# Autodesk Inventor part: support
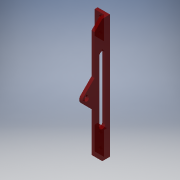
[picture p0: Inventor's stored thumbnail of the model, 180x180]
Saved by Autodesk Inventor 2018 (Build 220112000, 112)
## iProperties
Created: 2023-12
Part Number: support
Material: Generic
Document SubType Name: Modeling
Designer: DDUGKY
Density: 1 g/cm^3
Appearance: Default
Author: DDUGKY
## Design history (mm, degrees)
sketch "Sketch1"
  geometry: L1 (25, 200)-(0, 200); L2 (0, -200)-(25, -200); L3 (25, 200)-(-25, -200); L4 (-25, 200)-(25, -200); L5 (0, 100)-(0, -100); L6 (-10, 100)-(-10, -100); L7 (10, -100)-(10, 100); L8 (0, -200)-(-25, -175); L9 (-60.599, -10.614)-(-25, -46.213); L10 (-60.365, 10.848)-(-25, 46.213); L11 (-25, 175)-(-25, 46.213); L12 (-25, -46.213)-(-25, -175); L13 (25, 200)-(25, -200); L14 (0, 200)-(-25, 175); C1 r 7.5 at (-50, 0); A1 r 10 centre (0, 100) between (10, 100) and (-10, 100); A2 r 10 centre (0, -100) between (-10, -100) and (10, -100); A3 r 15.345 centre (-49.514, -0.003) between (-60.365, 10.848) and (-60.599, -10.614); 1 further point
  constraints: 30 end point, 6 point on circle, 5 tangent, 4 centre point, 4 vertical, 3 midpoint, 2 parallel, 1 horizontal, 1 perpendicular
  dimensions: "d0" = 50 distance of L2.end L3.end; "d1" = 400 distance of L3.end L4.start; "d5" = 100 distance of point (0, 0) L5.end; "d6" = 20 diameter of A2; "d15" = 15 diameter of C1
extrude "Extrusion3" new body sketch "Sketch1" distance "d17" = 10; taper "d18" = 0 deg
sketch "Sketch2"
  geometry: L1 (25, 200)-(0, 200) reference; L2 (25, 200)-(15, 200); L3 (15, 200)-(15, 125); L4 (15, 125)-(25, 125); L5 (25, 125)-(25, 200); L6 (25, -200)-(25, 200) reference; L7 (25, -200)-(15, -200); L8 (15, -200)-(15, -125); L9 (15, -125)-(25, -125); L10 (25, -125)-(25, -200); 1 further point
  constraints: 16 end point, 4 parallel, 2 horizontal, 2 perpendicular
  dimensions: "d19" = 10 distance of L4.end L3.end; "d20" = 75 distance of L3.end L2.end; "d21" = 10 distance of L8.end L9.end; "d22" = 75 distance of L7.end L8.end
extrude "Extrusion4" join sketch "Sketch2" distance "d23" = 30; taper "d24" = 0 deg
sketch "Sketch4"
  geometry: L1 (0, 200)-(0, 175) reference; L2 (-10, 200)-(30, 200) reference; L3 (0, 200)-(30, 200); L4 (0, 125)-(30, 125) reference; L5 (30, 125)-(0, 125); L6 (15, 200)-(15, 185); L7 (15, 125)-(15, 140); L8 (-36.984, 0)-(43.979, 0); L9 (0, -200)-(0, -175); L10 (-10, -200)-(30, -200); L11 (0, -200)-(30, -200); L12 (0, -125)-(30, -125); L13 (30, -125)-(0, -125); L14 (15, -200)-(15, -185); L15 (15, -125)-(15, -140); C1 r 3.75 at (15, 185); C2 r 3.75 at (15, 140); C3 r 3.75 at (15, -185); C4 r 3.75 at (15, -140); 1 further point
  constraints: 24 end point, 12 symmetric about line, 4 centre point, 4 coincident, 2 horizontal, 2 midpoint, 2 vertical, 1 collinear, 2 other
  dimensions: "d32" = 15 distance of L6.start L6.end; "d33" = 15 distance of L7.start L7.end; "d34" = 7.5 diameter of C1; "d35" = 7.5 diameter of C2
extrude "Extrusion6" cut sketch "Sketch4" distance "d36" = 31.25; taper "d37" = 0 deg
body "Solid3"
